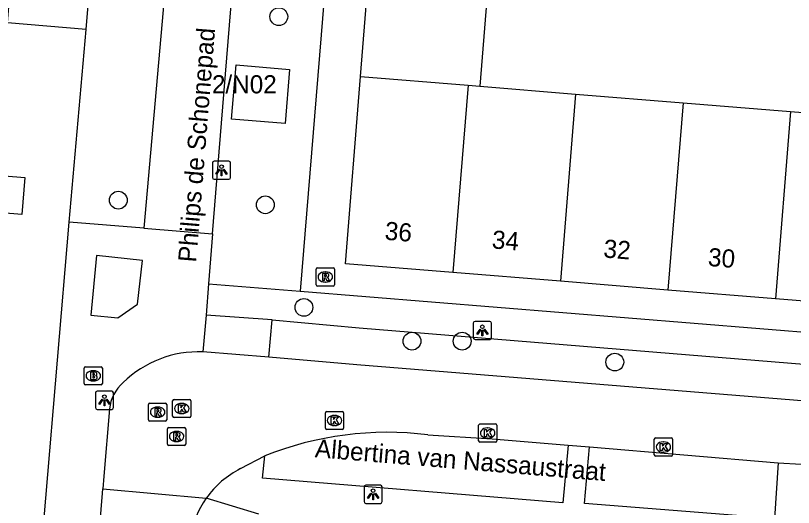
# Model space of a CAD drawing. Extents: x 159961 to 160856, y 382704 to 383353.
# Drawn here: x 160441.41 to 160484.26, y 383198.31 to 383225.38 of the extents above; entities that cross this region are included whole.
import ezdxf

# ---------------------------------------------------------------- set-up
doc = ezdxf.new("R2010")
doc.units = 0
for name, color, linetype in [('IMGEO_Boom', 7, 'Continuous'), ('IMGEO_Brandkraan', 7, 'Continuous'), ('IMGEO_Groenvoorziening', 7, 'Continuous'), ('IMGEO_Kolk', 7, 'Continuous'), ('IMGEO_Lichtpunt', 7, 'Continuous'), ('IMGEO_Openbare_ruimte_label', 7, 'Continuous'), ('IMGEO_Pand', 7, 'Continuous'), ('IMGEO_Pand_nummerreeks', 7, 'Continuous'), ('IMGEO_Parkeervlak_open', 7, 'Continuous'), ('IMGEO_Rijbaan_lokaal_open', 7, 'Continuous'), ('IMGEO_Rioolput', 7, 'Continuous'), ('IMGEO_Voetpad_open', 7, 'Continuous')]:
    doc.layers.add(name, color=color, linetype=linetype)

msp = doc.modelspace()

# ---------------------------------------------------------------- linework, layer by layer
at = {"layer": 'IMGEO_Boom'}
for centre in [(160455.91, 383225.326), (160447.071, 383215.223), (160455.168, 383214.968), (160457.292, 383209.322), (160463.245, 383207.461), (160466.009, 383207.461), (160474.417, 383206.309)]:
    msp.add_circle(centre, 0.489, dxfattribs=at)
at = {"layer": 'IMGEO_Brandkraan'}
for p, q in [((160445.193, 383205.13), (160445.193, 383205.982)), ((160445.268, 383206.056), (160446.12, 383206.056)), ((160445.681, 383205.836), (160445.706, 383205.836)), ((160446.194, 383205.982), (160446.194, 383205.13)), ((160446.12, 383205.056), (160445.268, 383205.056)), ((160445.704, 383205.276), (160445.679, 383205.276))]:
    msp.add_line(p, q, dxfattribs=at)
for points in [[(160445.193, 383205.13), (160445.193, 383205.982)], [(160445.268, 383206.056), (160446.12, 383206.056)], [(160445.541, 383205.756), (160445.541, 383205.356), (160445.754, 383205.356)], [(160445.772, 383205.756), (160445.541, 383205.756)], [(160446.194, 383205.982), (160446.194, 383205.13)], [(160445.72, 383205.675), (160445.666, 383205.675), (160445.666, 383205.599)], [(160445.666, 383205.599), (160445.719, 383205.599)], [(160445.728, 383205.523), (160445.666, 383205.523), (160445.666, 383205.442)], [(160445.666, 383205.442), (160445.728, 383205.442)], [(160446.12, 383205.056), (160445.268, 383205.056)]]:
    msp.add_lwpolyline(points, dxfattribs=at)
for centre, radius, start, end in [((160445.27, 383205.98), 0.0765, 91.552, 178.448), ((160445.27, 383205.98), 0.0765, 91.552, 178.448), ((160445.776, 383205.611), 0.145, 59.4692, 91.5367), ((160446.118, 383205.98), 0.0765, 1.552, 88.448), ((160446.118, 383205.98), 0.0765, 1.552, 88.448), ((160445.721, 383205.637), 0.0379, 267.8285, 90.9355), ((160445.729, 383205.482), 0.0404, 269.8759, 90.5077), ((160445.76, 383205.607), 0.251, 268.6676, 293.5347), ((160445.801, 383205.658), 0.0922, 285.5137, 58.1501), ((160445.806, 383205.466), 0.105, 301.3115, 78.989), ((160445.27, 383205.132), 0.0765, 181.552, 268.448), ((160445.27, 383205.132), 0.0765, 181.552, 268.448), ((160446.118, 383205.132), 0.0765, 271.552, 358.448), ((160446.118, 383205.132), 0.0765, 271.552, 358.448)]:
    msp.add_arc(centre, radius, start, end, dxfattribs=at)
for centre, major_axis, ratio, start_param, end_param in [((160445.68, 383205.556), (-0.387, 0.002), 0.722429, 4.712389, 7.853982), ((160445.705, 383205.556), (-0.39, 0.002), 0.717154, 1.570796, 4.712389)]:
    msp.add_ellipse(centre, major_axis=major_axis, ratio=ratio, start_param=start_param, end_param=end_param, dxfattribs=at)
at = {"layer": 'IMGEO_Groenvoorziening'}
msp.add_lwpolyline([(160444.36, 383214.015), (160445.309, 383224.622)], dxfattribs=at)
at = {"layer": 'IMGEO_Kolk'}
for p, q in [((160450.064, 383203.326), (160450.064, 383204.178)), ((160450.139, 383204.252), (160450.991, 383204.252)), ((160450.552, 383204.032), (160450.577, 383204.032)), ((160451.065, 383204.178), (160451.065, 383203.326)), ((160458.553, 383203.598), (160459.405, 383203.598)), ((160450.991, 383203.252), (160450.139, 383203.252)), ((160450.575, 383203.472), (160450.55, 383203.472)), ((160458.478, 383202.672), (160458.478, 383203.524)), ((160458.966, 383203.378), (160458.991, 383203.378)), ((160459.479, 383203.524), (160459.479, 383202.672)), ((160458.989, 383202.818), (160458.964, 383202.818)), ((160466.914, 383201.978), (160466.914, 383202.83)), ((160466.989, 383202.904), (160467.841, 383202.904)), ((160467.915, 383202.83), (160467.915, 383201.978)), ((160459.405, 383202.598), (160458.553, 383202.598)), ((160467.402, 383202.684), (160467.427, 383202.684)), ((160467.841, 383201.904), (160466.989, 383201.904)), ((160467.425, 383202.124), (160467.4, 383202.124)), ((160476.591, 383201.21), (160476.591, 383202.062)), ((160476.666, 383202.136), (160477.518, 383202.136)), ((160477.079, 383201.916), (160477.104, 383201.916)), ((160477.592, 383202.062), (160477.592, 383201.21)), ((160477.518, 383201.136), (160476.666, 383201.136)), ((160477.102, 383201.356), (160477.077, 383201.356))]:
    msp.add_line(p, q, dxfattribs=at)
for points in [[(160450.064, 383203.326), (160450.064, 383204.178)], [(160450.139, 383204.252), (160450.991, 383204.252)], [(160451.065, 383204.178), (160451.065, 383203.326)], [(160450.385, 383203.952), (160450.508, 383203.952), (160450.508, 383203.801), (160450.638, 383203.952), (160450.802, 383203.952), (160450.656, 383203.801), (160450.809, 383203.552), (160450.657, 383203.552), (160450.572, 383203.716), (160450.508, 383203.649), (160450.508, 383203.552), (160450.385, 383203.552), (160450.385, 383203.952)], [(160458.553, 383203.598), (160459.405, 383203.598)], [(160450.991, 383203.252), (160450.139, 383203.252)], [(160458.478, 383202.672), (160458.478, 383203.524)], [(160458.799, 383203.298), (160458.922, 383203.298), (160458.922, 383203.147), (160459.052, 383203.298), (160459.216, 383203.298), (160459.07, 383203.147), (160459.223, 383202.898), (160459.071, 383202.898), (160458.986, 383203.062), (160458.922, 383202.995), (160458.922, 383202.898), (160458.799, 383202.898), (160458.799, 383203.298)], [(160459.479, 383203.524), (160459.479, 383202.672)], [(160466.914, 383201.978), (160466.914, 383202.83)], [(160466.989, 383202.904), (160467.841, 383202.904)], [(160467.915, 383202.83), (160467.915, 383201.978)], [(160459.405, 383202.598), (160458.553, 383202.598)], [(160467.235, 383202.604), (160467.358, 383202.604), (160467.358, 383202.453), (160467.488, 383202.604), (160467.652, 383202.604), (160467.506, 383202.453), (160467.659, 383202.204), (160467.507, 383202.204), (160467.422, 383202.368), (160467.358, 383202.301), (160467.358, 383202.204), (160467.235, 383202.204), (160467.235, 383202.604)], [(160467.841, 383201.904), (160466.989, 383201.904)], [(160476.591, 383201.21), (160476.591, 383202.062)], [(160476.666, 383202.136), (160477.518, 383202.136)], [(160477.592, 383202.062), (160477.592, 383201.21)], [(160476.912, 383201.836), (160477.035, 383201.836), (160477.035, 383201.685), (160477.165, 383201.836), (160477.329, 383201.836), (160477.183, 383201.685), (160477.336, 383201.436), (160477.184, 383201.436), (160477.099, 383201.6), (160477.035, 383201.533), (160477.035, 383201.436), (160476.912, 383201.436), (160476.912, 383201.836)], [(160477.518, 383201.136), (160476.666, 383201.136)]]:
    msp.add_lwpolyline(points, dxfattribs=at)
for centre, start, end in [((160450.141, 383204.176), 91.552, 178.448), ((160450.141, 383204.176), 91.552, 178.448), ((160450.989, 383204.176), 1.552, 88.448), ((160450.989, 383204.176), 1.552, 88.448), ((160458.555, 383203.522), 91.552, 178.448), ((160458.555, 383203.522), 91.552, 178.448), ((160459.403, 383203.522), 1.552, 88.448), ((160459.403, 383203.522), 1.552, 88.448), ((160450.141, 383203.328), 181.552, 268.448), ((160450.141, 383203.328), 181.552, 268.448), ((160450.989, 383203.328), 271.552, 358.448), ((160450.989, 383203.328), 271.552, 358.448), ((160466.991, 383202.828), 91.552, 178.448), ((160466.991, 383202.828), 91.552, 178.448), ((160467.839, 383202.828), 1.552, 88.448), ((160467.839, 383202.828), 1.552, 88.448), ((160458.555, 383202.674), 181.552, 268.448), ((160458.555, 383202.674), 181.552, 268.448), ((160459.403, 383202.674), 271.552, 358.448), ((160459.403, 383202.674), 271.552, 358.448), ((160466.991, 383201.98), 181.552, 268.448), ((160466.991, 383201.98), 181.552, 268.448), ((160467.839, 383201.98), 271.552, 358.448), ((160467.839, 383201.98), 271.552, 358.448), ((160476.668, 383202.06), 91.552, 178.448), ((160476.668, 383202.06), 91.552, 178.448), ((160477.516, 383202.06), 1.552, 88.448), ((160477.516, 383202.06), 1.552, 88.448), ((160476.668, 383201.212), 181.552, 268.448), ((160476.668, 383201.212), 181.552, 268.448), ((160477.516, 383201.212), 271.552, 358.448), ((160477.516, 383201.212), 271.552, 358.448)]:
    msp.add_arc(centre, 0.0765, start, end, dxfattribs=at)
for centre, major_axis, ratio, start_param, end_param in [((160450.551, 383203.752), (-0.387, 0.002), 0.722429, 4.712389, 7.853982), ((160450.576, 383203.752), (-0.39, 0.002), 0.717154, 1.570796, 4.712389), ((160458.965, 383203.098), (-0.387, 0.002), 0.722429, 4.712389, 7.853982), ((160458.99, 383203.098), (-0.39, 0.002), 0.717154, 1.570796, 4.712389), ((160467.401, 383202.404), (-0.387, 0.002), 0.722429, 4.712389, 7.853982), ((160467.426, 383202.404), (-0.39, 0.002), 0.717154, 1.570796, 4.712389), ((160477.078, 383201.636), (-0.387, 0.002), 0.722429, 4.712389, 7.853982), ((160477.103, 383201.636), (-0.39, 0.002), 0.717154, 1.570796, 4.712389)]:
    msp.add_ellipse(centre, major_axis=major_axis, ratio=ratio, start_param=start_param, end_param=end_param, dxfattribs=at)
at = {"layer": 'IMGEO_Lichtpunt'}
for p, q in [((160453.16, 383217.367), (160452.352, 383217.367)), ((160453.16, 383217.367), (160452.352, 383217.367)), ((160452.258, 383217.272), (160452.258, 383216.465)), ((160452.258, 383217.272), (160452.258, 383216.465)), ((160453.254, 383216.465), (160453.254, 383217.272)), ((160453.254, 383216.465), (160453.254, 383217.272)), ((160452.352, 383216.371), (160453.16, 383216.371)), ((160452.352, 383216.371), (160453.16, 383216.371)), ((160466.624, 383208.456), (160466.624, 383207.649)), ((160466.624, 383208.456), (160466.624, 383207.649)), ((160467.526, 383208.551), (160466.718, 383208.551)), ((160467.526, 383208.551), (160466.718, 383208.551)), ((160467.62, 383207.649), (160467.62, 383208.456)), ((160467.62, 383207.649), (160467.62, 383208.456)), ((160466.718, 383207.555), (160467.526, 383207.555)), ((160466.718, 383207.555), (160467.526, 383207.555)), ((160445.81, 383204.61), (160445.81, 383203.803)), ((160445.81, 383204.61), (160445.81, 383203.803)), ((160446.712, 383204.705), (160445.904, 383204.705)), ((160446.712, 383204.705), (160445.904, 383204.705)), ((160446.806, 383203.803), (160446.806, 383204.61)), ((160446.806, 383203.803), (160446.806, 383204.61)), ((160445.904, 383203.709), (160446.712, 383203.709)), ((160445.904, 383203.709), (160446.712, 383203.709)), ((160460.605, 383199.435), (160460.605, 383198.628)), ((160460.605, 383199.435), (160460.605, 383198.628)), ((160461.507, 383199.53), (160460.699, 383199.53)), ((160461.507, 383199.53), (160460.699, 383199.53)), ((160461.601, 383198.628), (160461.601, 383199.435)), ((160461.601, 383198.628), (160461.601, 383199.435)), ((160460.699, 383198.534), (160461.507, 383198.534)), ((160460.699, 383198.534), (160461.507, 383198.534))]:
    msp.add_line(p, q, dxfattribs=at)
for points in [[(160452.632, 383216.936), (160452.671, 383216.908), (160452.483, 383216.646), (160452.445, 383216.673), (160452.632, 383216.936)], [(160452.734, 383216.888), (160452.781, 383216.888), (160452.781, 383216.566), (160452.734, 383216.566), (160452.734, 383216.888)], [(160452.844, 383216.908), (160452.882, 383216.935), (160453.069, 383216.673), (160453.03, 383216.645), (160452.844, 383216.908)], [(160466.998, 383208.12), (160467.037, 383208.092), (160466.849, 383207.83), (160466.811, 383207.857), (160466.998, 383208.12)], [(160467.1, 383208.072), (160467.147, 383208.072), (160467.147, 383207.75), (160467.1, 383207.75), (160467.1, 383208.072)], [(160467.21, 383208.092), (160467.248, 383208.119), (160467.435, 383207.857), (160467.396, 383207.829), (160467.21, 383208.092)], [(160446.184, 383204.274), (160446.223, 383204.246), (160446.035, 383203.984), (160445.997, 383204.011), (160446.184, 383204.274)], [(160446.286, 383204.226), (160446.333, 383204.226), (160446.333, 383203.904), (160446.286, 383203.904), (160446.286, 383204.226)], [(160446.396, 383204.246), (160446.434, 383204.273), (160446.621, 383204.011), (160446.582, 383203.983), (160446.396, 383204.246)], [(160460.979, 383199.099), (160461.018, 383199.071), (160460.83, 383198.809), (160460.792, 383198.836), (160460.979, 383199.099)], [(160461.081, 383199.051), (160461.128, 383199.051), (160461.128, 383198.729), (160461.081, 383198.729), (160461.081, 383199.051)], [(160461.191, 383199.071), (160461.229, 383199.098), (160461.416, 383198.836), (160461.377, 383198.808), (160461.191, 383199.071)]]:
    msp.add_lwpolyline(points, dxfattribs=at)
for centre in [(160452.757, 383217.07), (160467.123, 383208.254), (160446.309, 383204.408), (160461.104, 383199.233)]:
    msp.add_circle(centre, 0.0994, dxfattribs=at)
for centre, start, end in [((160452.352, 383217.272), 90, 180), ((160452.352, 383217.272), 90, 180), ((160453.16, 383217.272), 0, 90), ((160453.16, 383217.272), 0, 90), ((160452.352, 383216.465), 180, 270), ((160452.352, 383216.465), 180, 270), ((160453.16, 383216.465), 270, 0), ((160453.16, 383216.465), 270, 360), ((160466.718, 383208.456), 90, 180), ((160466.718, 383208.456), 90, 180), ((160467.526, 383208.456), 0, 90), ((160467.526, 383208.456), 0, 90), ((160466.718, 383207.649), 180, 270), ((160466.718, 383207.649), 180, 270), ((160467.526, 383207.649), 270, 0), ((160467.526, 383207.649), 270, 360), ((160445.904, 383204.61), 90, 180), ((160445.904, 383204.61), 90, 180), ((160446.712, 383204.61), 0, 90), ((160446.712, 383204.61), 0, 90), ((160445.904, 383203.803), 180, 270), ((160445.904, 383203.803), 180, 270), ((160446.712, 383203.803), 270, 0), ((160446.712, 383203.803), 270, 360), ((160460.699, 383199.435), 90, 180), ((160460.699, 383199.435), 90, 180), ((160461.507, 383199.435), 0, 90), ((160461.507, 383199.435), 0, 90), ((160460.699, 383198.628), 180, 270), ((160460.699, 383198.628), 180, 270), ((160461.507, 383198.628), 270, 0), ((160461.507, 383198.628), 270, 360)]:
    msp.add_arc(centre, 0.0946, start, end, dxfattribs=at)
at = {"layer": 'IMGEO_Pand'}
for points in [[(160460.405, 383222.025), (160461.14, 383231.161), (160461.151, 383231.299)], [(160467.713, 383230.633), (160466.978, 383221.493)], [(160445.309, 383224.622), (160440.965, 383224.979), (160441.075, 383226.317), (160437.761, 383226.591), (160437.997, 383229.454)], [(160445.309, 383224.622), (160445.692, 383229.286)], [(160456.501, 383222.423), (160456.255, 383219.44), (160453.311, 383219.683), (160453.557, 383222.666), (160456.501, 383222.423)], [(160465.497, 383211.238), (160459.576, 383211.718), (160460.405, 383222.025)], [(160460.405, 383222.025), (160466.332, 383221.545)], [(160466.332, 383221.545), (160465.497, 383211.238)], [(160466.332, 383221.545), (160466.978, 383221.493)], [(160466.978, 383221.493), (160472.253, 383221.066)], [(160472.253, 383221.066), (160471.418, 383210.758)], [(160472.253, 383221.066), (160478.174, 383220.586)], [(160478.174, 383220.586), (160477.339, 383210.278)], [(160478.174, 383220.586), (160484.095, 383220.106)], [(160484.095, 383220.106), (160483.26, 383209.798)], [(160484.095, 383220.106), (160490.017, 383219.627)], [(160436.961, 383216.873), (160441.927, 383216.472), (160441.762, 383214.437), (160436.793, 383214.839)], [(160471.418, 383210.758), (160465.497, 383211.238)], [(160477.339, 383210.278), (160471.418, 383210.758)], [(160483.26, 383209.798), (160477.339, 383210.278)], [(160489.181, 383209.318), (160483.26, 383209.798)]]:
    msp.add_lwpolyline(points, dxfattribs=at)
at = {"layer": 'IMGEO_Parkeervlak_open'}
msp.add_lwpolyline([(160455.354, 383206.572), (160455.55, 383208.627)], dxfattribs=at)
at = {"layer": 'IMGEO_Rijbaan_lokaal_open'}
for points in [[(160455.354, 383206.572), (160451.725, 383206.868)], [(160505.82, 383202.464), (160460.211, 383206.166), (160455.354, 383206.572)], [(160446.579, 383203.728), (160446.265, 383200.034), (160446.213, 383199.341)], [(160464.123, 383202.305), (160467.667, 383202.088), (160471.84, 383201.732)], [(160471.84, 383201.732), (160473.024, 383201.651)], [(160473.024, 383201.651), (160483.417, 383200.773)], [(160453.803, 383200.444), (160455.14, 383201.141)], [(160483.417, 383200.773), (160484.68, 383200.693)], [(160442.381, 383152.727), (160442.403, 383152.848), (160442.458, 383153.658), (160443.021, 383160.036), (160443.691, 383168.249), (160444.785, 383181.786), (160445.421, 383189.575), (160445.681, 383192.81), (160446.195, 383199.097), (160446.213, 383199.341)], [(160446.213, 383199.341), (160451.918, 383198.823)]]:
    msp.add_lwpolyline(points, dxfattribs=at)
for centre, radius, start, end in [((160451.479, 383200.969), 5.904, 87.616, 134.5011), ((160448.902, 383203.435), 2.342, 131.8159, 172.8037), ((160461.883, 383184.348), 18.097, 82.8897, 111.8766), ((160456.178, 383195.775), 5.238, 116.9665, 144.4211), ((160455.913, 383196.01), 4.886, 144.8466, 173.7332)]:
    msp.add_arc(centre, radius, start, end, dxfattribs=at)
at = {"layer": 'IMGEO_Rioolput'}
for p, q in [((160457.972, 383210.569), (160457.972, 383211.421)), ((160458.047, 383211.495), (160458.899, 383211.495)), ((160458.973, 383211.421), (160458.973, 383210.569)), ((160458.46, 383211.275), (160458.485, 383211.275)), ((160458.899, 383210.495), (160458.047, 383210.495)), ((160458.483, 383210.715), (160458.458, 383210.715)), ((160448.812, 383204.054), (160449.664, 383204.054)), ((160448.737, 383203.128), (160448.737, 383203.98)), ((160449.225, 383203.834), (160449.25, 383203.834)), ((160449.738, 383203.98), (160449.738, 383203.128)), ((160449.248, 383203.274), (160449.223, 383203.274)), ((160449.664, 383203.054), (160448.812, 383203.054)), ((160449.782, 383201.79), (160449.782, 383202.642)), ((160449.857, 383202.716), (160450.709, 383202.716)), ((160450.27, 383202.496), (160450.295, 383202.496)), ((160450.783, 383202.642), (160450.783, 383201.79)), ((160450.293, 383201.936), (160450.268, 383201.936)), ((160450.709, 383201.716), (160449.857, 383201.716))]:
    msp.add_line(p, q, dxfattribs=at)
for points in [[(160457.972, 383210.569), (160457.972, 383211.421)], [(160458.047, 383211.495), (160458.899, 383211.495)], [(160458.973, 383211.421), (160458.973, 383210.569)], [(160458.561, 383211.193), (160458.309, 383211.195), (160458.309, 383210.795)], [(160458.309, 383210.795), (160458.433, 383210.795), (160458.433, 383210.957), (160458.444, 383210.957)], [(160458.487, 383211.114), (160458.433, 383211.114), (160458.433, 383211.033)], [(160458.433, 383211.033), (160458.485, 383211.033)], [(160458.491, 383210.928), (160458.562, 383210.795), (160458.702, 383210.795), (160458.637, 383210.921)], [(160458.899, 383210.495), (160458.047, 383210.495)], [(160448.812, 383204.054), (160449.664, 383204.054)], [(160448.737, 383203.128), (160448.737, 383203.98)], [(160449.326, 383203.752), (160449.074, 383203.754), (160449.074, 383203.354)], [(160449.252, 383203.673), (160449.198, 383203.673), (160449.198, 383203.592)], [(160449.738, 383203.98), (160449.738, 383203.128)], [(160449.074, 383203.354), (160449.198, 383203.354), (160449.198, 383203.516), (160449.209, 383203.516)], [(160449.198, 383203.592), (160449.25, 383203.592)], [(160449.256, 383203.487), (160449.327, 383203.354), (160449.467, 383203.354), (160449.402, 383203.48)], [(160449.664, 383203.054), (160448.812, 383203.054)], [(160449.782, 383201.79), (160449.782, 383202.642)], [(160449.857, 383202.716), (160450.709, 383202.716)], [(160450.371, 383202.414), (160450.119, 383202.416), (160450.119, 383202.016)], [(160450.297, 383202.335), (160450.243, 383202.335), (160450.243, 383202.254)], [(160450.783, 383202.642), (160450.783, 383201.79)], [(160450.119, 383202.016), (160450.243, 383202.016), (160450.243, 383202.178), (160450.254, 383202.178)], [(160450.243, 383202.254), (160450.295, 383202.254)], [(160450.301, 383202.149), (160450.372, 383202.016), (160450.512, 383202.016), (160450.447, 383202.142)], [(160450.709, 383201.716), (160449.857, 383201.716)]]:
    msp.add_lwpolyline(points, dxfattribs=at)
for centre, radius, start, end in [((160458.049, 383211.419), 0.0765, 91.552, 178.448), ((160458.049, 383211.419), 0.0765, 91.552, 178.448), ((160458.897, 383211.419), 0.0765, 1.552, 88.448), ((160458.897, 383211.419), 0.0765, 1.552, 88.448), ((160458.443, 383210.904), 0.0533, 26.0293, 88.6989), ((160458.469, 383211.222), 0.19, 274.7715, 282.9687), ((160458.493, 383211.018), 0.0964, 77.0061, 93.1865), ((160458.507, 383211.075), 0.0378, 276.6634, 79.6772), ((160458.56, 383211.083), 0.109, 350.3612, 89.416), ((160458.558, 383211.083), 0.112, 277.5842, 350.9817), ((160458.542, 383210.868), 0.108, 29.5134, 73.7905), ((160458.049, 383210.571), 0.0765, 181.552, 268.448), ((160458.049, 383210.571), 0.0765, 181.552, 268.448), ((160458.897, 383210.571), 0.0765, 271.552, 358.448), ((160458.897, 383210.571), 0.0765, 271.552, 358.448), ((160448.814, 383203.978), 0.0765, 91.552, 178.448), ((160448.814, 383203.978), 0.0765, 91.552, 178.448), ((160449.662, 383203.978), 0.0765, 1.552, 88.448), ((160449.662, 383203.978), 0.0765, 1.552, 88.448), ((160449.258, 383203.577), 0.0964, 77.0061, 93.1865), ((160449.272, 383203.634), 0.0378, 276.6634, 79.6772), ((160449.325, 383203.642), 0.109, 350.3612, 89.416), ((160449.323, 383203.642), 0.112, 277.5842, 350.9817), ((160449.208, 383203.463), 0.0533, 26.0293, 88.6989), ((160449.234, 383203.781), 0.19, 274.7715, 282.9687), ((160449.307, 383203.427), 0.108, 29.5134, 73.7905), ((160448.814, 383203.13), 0.0765, 181.552, 268.448), ((160448.814, 383203.13), 0.0765, 181.552, 268.448), ((160449.662, 383203.13), 0.0765, 271.552, 358.448), ((160449.662, 383203.13), 0.0765, 271.552, 358.448), ((160449.859, 383202.64), 0.0765, 91.552, 178.448), ((160449.859, 383202.64), 0.0765, 91.552, 178.448), ((160450.303, 383202.239), 0.0964, 77.0061, 93.1865), ((160450.317, 383202.296), 0.0378, 276.6634, 79.6772), ((160450.37, 383202.304), 0.109, 350.3612, 89.416), ((160450.707, 383202.64), 0.0765, 1.552, 88.448), ((160450.707, 383202.64), 0.0765, 1.552, 88.448), ((160450.253, 383202.125), 0.0533, 26.0293, 88.6989), ((160450.279, 383202.443), 0.19, 274.7715, 282.9687), ((160450.368, 383202.304), 0.112, 277.5842, 350.9817), ((160450.352, 383202.089), 0.108, 29.5134, 73.7905), ((160449.859, 383201.792), 0.0765, 181.552, 268.448), ((160449.859, 383201.792), 0.0765, 181.552, 268.448), ((160450.707, 383201.792), 0.0765, 271.552, 358.448), ((160450.707, 383201.792), 0.0765, 271.552, 358.448)]:
    msp.add_arc(centre, radius, start, end, dxfattribs=at)
for centre, major_axis, ratio, start_param, end_param in [((160458.459, 383210.995), (-0.387, 0.002), 0.722429, 4.712389, 7.853982), ((160458.484, 383210.995), (-0.39, 0.002), 0.717154, 1.570796, 4.712389), ((160449.224, 383203.554), (-0.387, 0.002), 0.722429, 4.712389, 7.853982), ((160449.249, 383203.554), (-0.39, 0.002), 0.717154, 1.570796, 4.712389), ((160450.269, 383202.216), (-0.387, 0.002), 0.722429, 4.712389, 7.853982), ((160450.294, 383202.216), (-0.39, 0.002), 0.717154, 1.570796, 4.712389)]:
    msp.add_ellipse(centre, major_axis=major_axis, ratio=ratio, start_param=start_param, end_param=end_param, dxfattribs=at)
at = {"layer": 'IMGEO_Voetpad_open'}
for points in [[(160452.266, 383213.376), (160452.763, 383219.455), (160459.993, 383308.019)], [(160462.297, 383273.845), (160457.086, 383210.211)], [(160451.071, 383242.904), (160449.03, 383219.895), (160448.479, 383213.682)], [(160439.206, 383153.248), (160444.36, 383214.015)], [(160448.479, 383213.682), (160444.36, 383214.015)], [(160448.479, 383213.682), (160452.266, 383213.376)], [(160452.266, 383213.376), (160452.046, 383210.622)], [(160445.556, 383208.887), (160447.042, 383208.748), (160448.12, 383209.491), (160448.406, 383211.909), (160445.864, 383212.178), (160445.556, 383208.887)], [(160452.046, 383210.622), (160451.909, 383208.902)], [(160452.046, 383210.622), (160457.086, 383210.211)], [(160457.086, 383210.211), (160507.719, 383206.111), (160507.543, 383203.899), (160532.407, 383201.802), (160543.672, 383200.881), (160554.232, 383199.98), (160566.784, 383199.039), (160566.841, 383199.647), (160578.819, 383198.623)], [(160451.909, 383208.902), (160451.725, 383206.868)], [(160455.55, 383208.627), (160451.909, 383208.902)], [(160455.55, 383208.627), (160460.328, 383208.187), (160505.945, 383204.477), (160505.82, 383202.464)], [(160471.84, 383201.732), (160471.553, 383198.562), (160455.013, 383199.919), (160455.14, 383201.141)], [(160483.417, 383200.773), (160483.215, 383197.708), (160472.752, 383198.519), (160473.024, 383201.651)], [(160454.816, 383197.945), (160451.918, 383198.823)]]:
    msp.add_lwpolyline(points, dxfattribs=at)

# ---------------------------------------------------------------- texts
at = {"layer": 'IMGEO_Openbare_ruimte_label'}
for s, rotation, p in [('Philips de Schonepad', 85.3553, (160451.358, 383211.776)), ('Albertina van Nassaustraat', 355.2982, (160457.878, 383201.079))]:
    msp.add_text(s, height=1, rotation=rotation, dxfattribs=at).set_placement(p)
at = {"layer": 'IMGEO_Pand_nummerreeks'}
msp.add_text('2/N02', height=1, dxfattribs=at).set_placement((160452.229, 383221.102))
for s, p in [('36', (160461.722, 383213.049)), ('34', (160467.621, 383212.571)), ('32', (160473.765, 383212.073)), ('30', (160479.519, 383211.606))]:
    msp.add_text(s, height=1, rotation=355.3648, dxfattribs=at).set_placement(p)

doc.saveas('drawing.dxf')
